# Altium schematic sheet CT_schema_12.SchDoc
size 145 x 119 mm
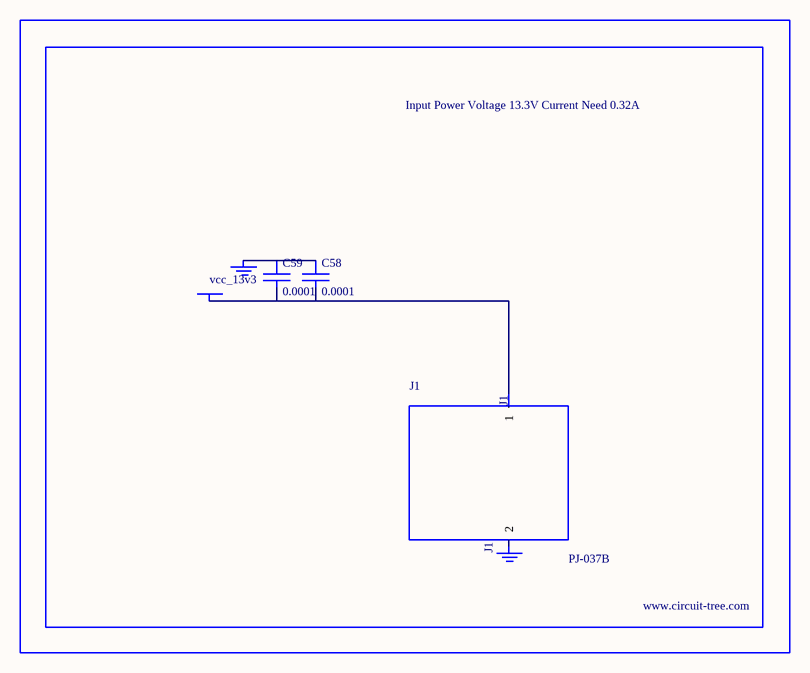
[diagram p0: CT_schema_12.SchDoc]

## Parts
BORDER11  (no value)
C58  0.0001  [EXV-9H]
C59  0.0001  [EXV-9H]
GND_INSTANCE_11_0  (no value)
GND_INSTANCE_11_1  (no value)
J1  PJ-037B  [PJ-037B_PACKAGE]
POWER_INSTANCE_11_0  vcc_13v3

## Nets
NetC58_1: C58.1 C59.1 GND_INSTANCE_11_0.0(GND)
NetC58_2: C58.2 C59.2 J1.1 POWER_INSTANCE_11_0.0(PWR)

Not connected (* = marked no-connect by the designer): GND_INSTANCE_11_1 0(GND); J1 2

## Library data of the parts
BORDER11 = BORDER_PAGE11
C58 C59 = EDK107M035A9HAA
GND_INSTANCE_11_0 GND_INSTANCE_11_1 = GND
POWER_INSTANCE_11_0 = PWR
